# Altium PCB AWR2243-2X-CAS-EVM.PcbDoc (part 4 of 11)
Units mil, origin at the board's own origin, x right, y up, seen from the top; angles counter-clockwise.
Board outline 5118.11 x 3937.01 mil, 8 copper layers (Layer 1 - Top Layer, Layer 2 - GND, Layer 3 - Signal (Sensitive), Layer 4 - GND / Signal, Layer 5 - Signal, Layer 6 - PWR / Signal, Layer 7 - GND, Layer 8 - Bottom Layer), stack 54.8 mil thick; 629 components, 407 nets, 2243 pads, 3950 vias.
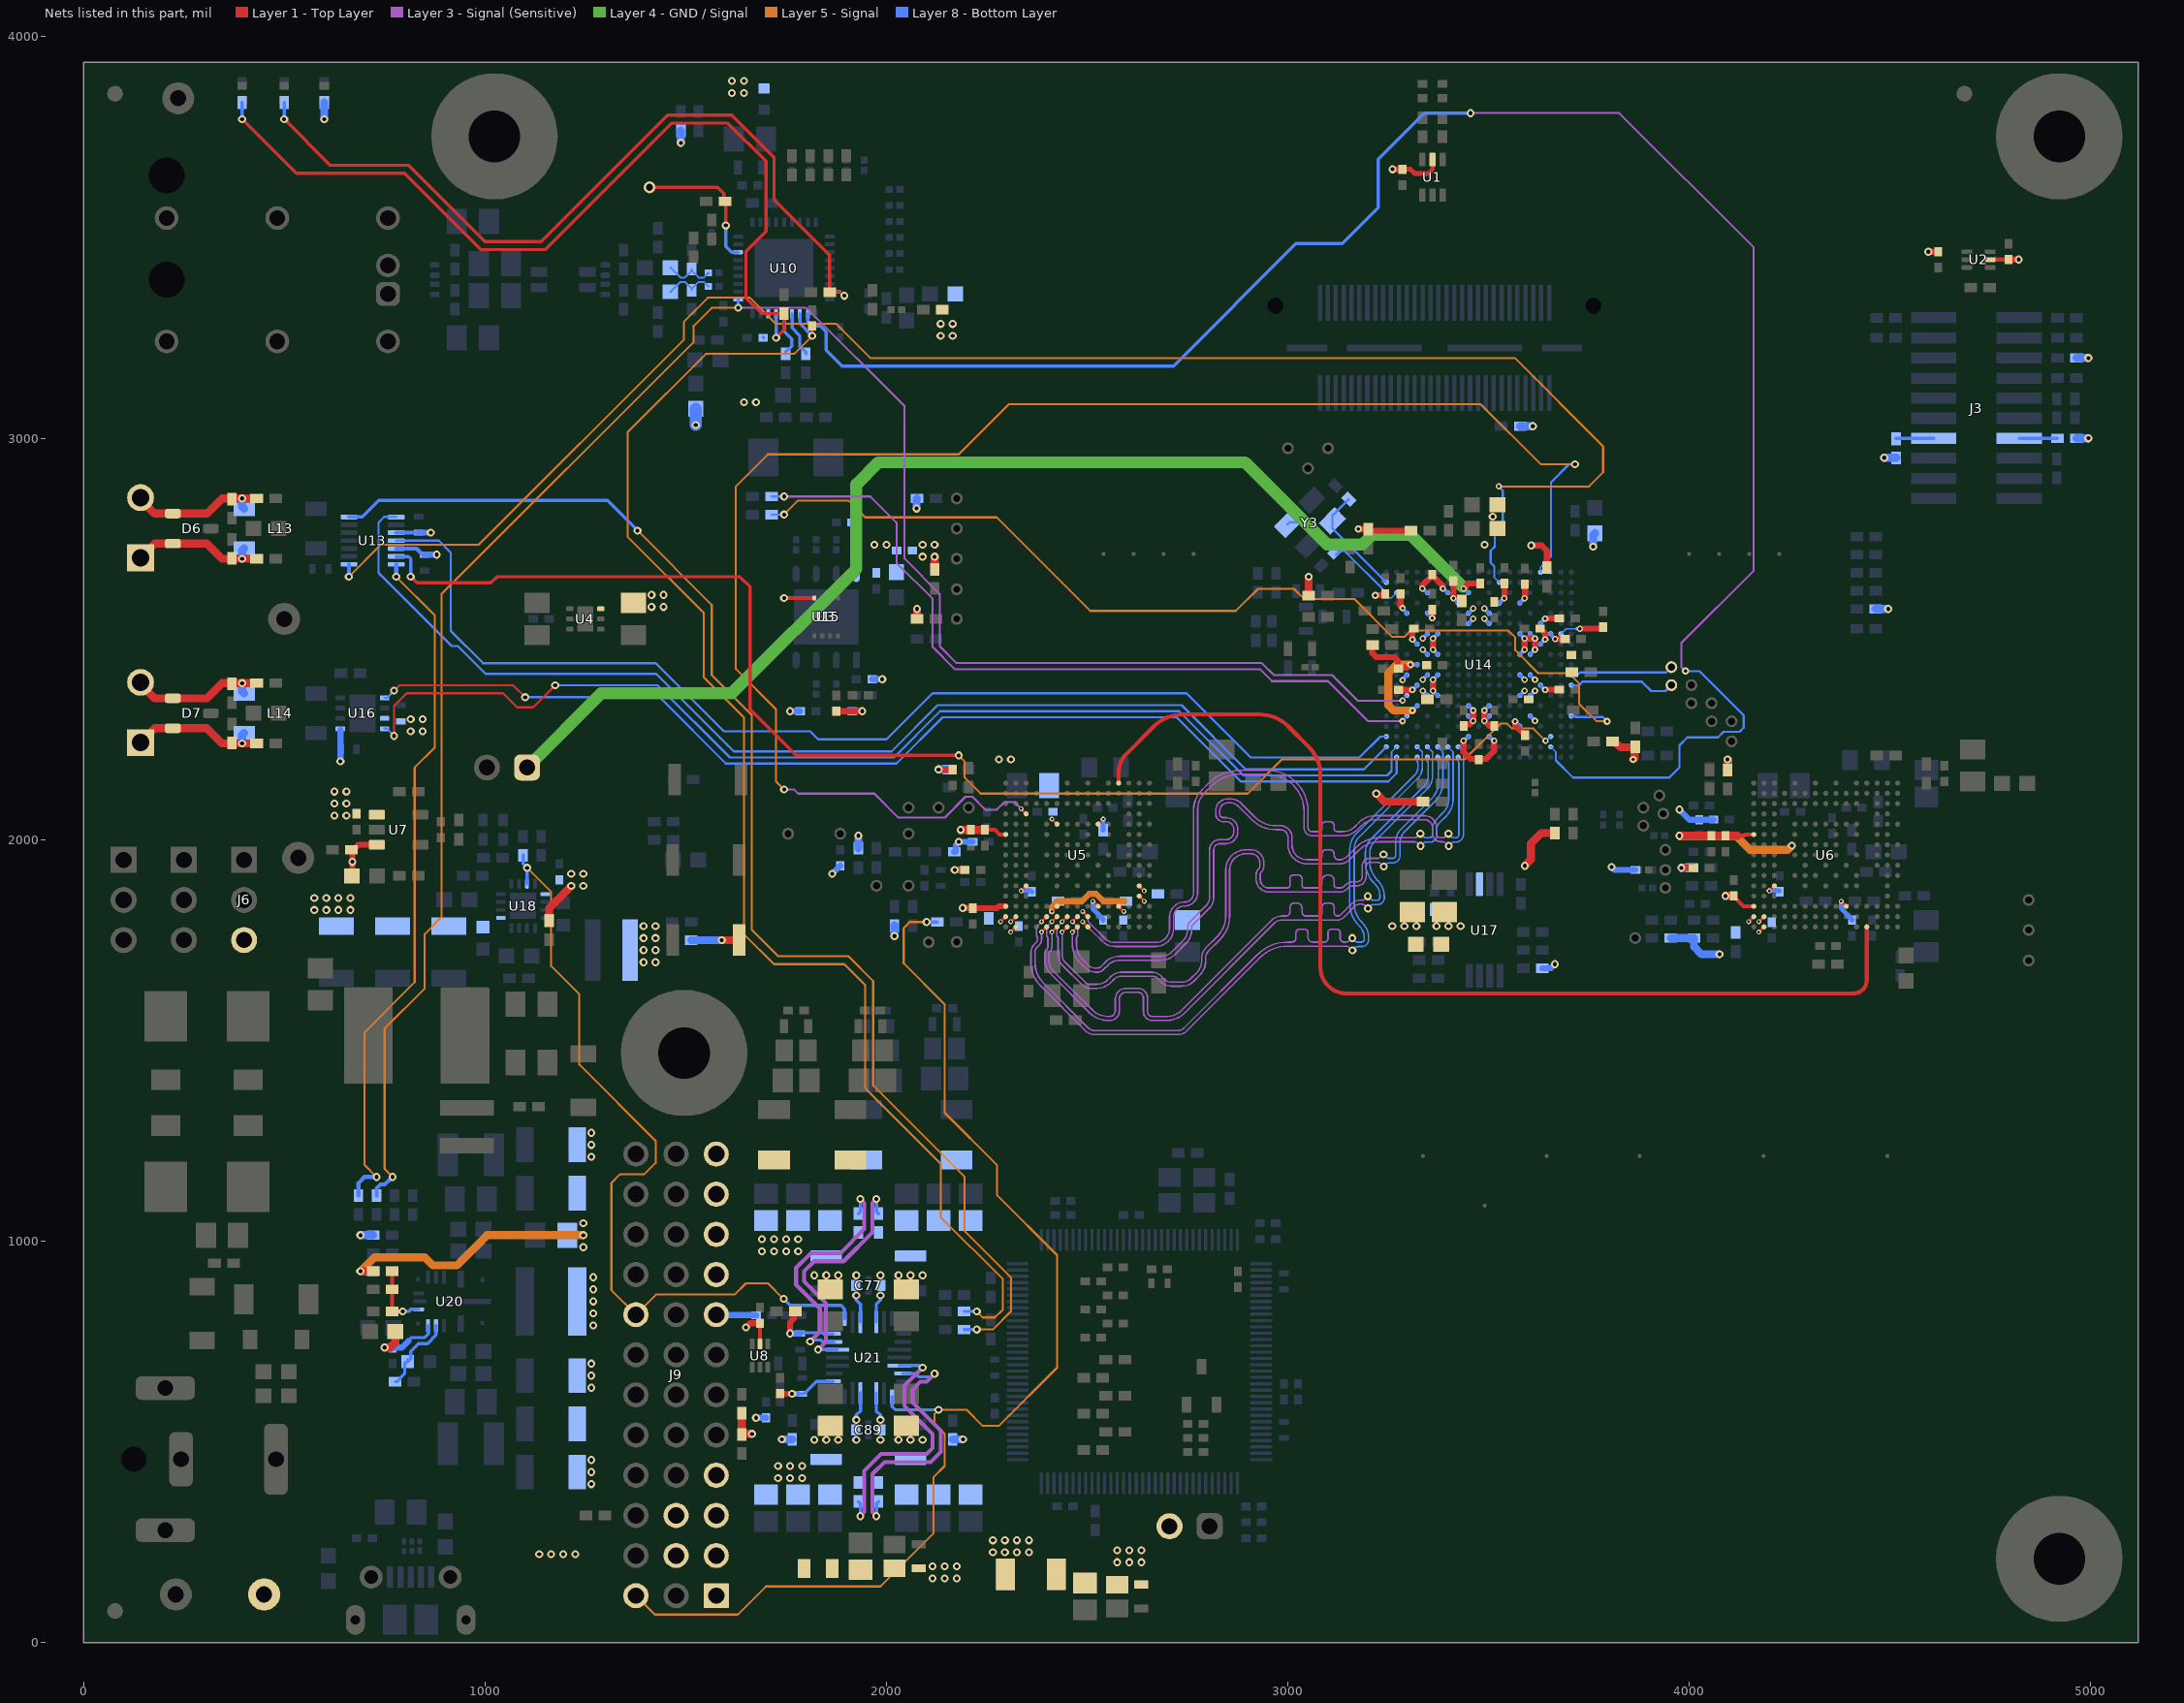
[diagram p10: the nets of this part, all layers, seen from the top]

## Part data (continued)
U1: library part CMP-0051906-3, "Automotive Catalog Dual Schmitt-Trigger Buffer, DCK0006A (SOT-SC70-6)", F @ Nom Voltage(Max)(Mhz)=150, Generic Part Number=SN74LVC2G17-Q1, ICC @ Nom Voltage(Max)(mA)=0.01, Manufacturer="Texas Instruments", Operating Temperature Range="-40 to 125 C", Rating=Automotive, tpd @ Nom Voltage(Max)(ns)=9.3,5.7,5.4,4.3, Voltage(Nom)(V)=1.8,2.5,3.3,5
U2 U8: library part CMP-0067397-2, "1.4V-Capable +/-0.5degC Temperature Sensor with Alert Function and I2C/SMBus interface in SOT-563, DRL0006A (SOT-OTHER-6)", Alternate Manufacturer="Texas Instruments", Alternate PartNumber=TMP112AIDRLT
U3: library part CMP-0089721-1, "FLASH - NOR Memory IC 16Mb (2M x 8) SPI 80MHz 8-USON (2x3)", Frequency_Fixed=80MHz, Manufacturer=Macronix, Max Supply Voltage=3.6V, Min Supply Voltage=2.3V, Nominal Supply Current=3.5-6.5mA, Operating Temperature Range="-40°C to +85°C"
U4: library part CMP-0860463-1, "Automotive 150-mA high-voltage ultra-low-IQ low-dropout (LDO) linear regulator, DRV0006A (WSON-6)", Alternate Manufacturer="Texas Instruments", Operating Temperature Range="-40 to 150 C", Rating=Automotive
U5 U6: library part CMP-0082537-1, "Single Chip 77 and 79 GHz FMCW Transceiver, ABL0161A (FCBGA-161)", Alternate Manufacturer="Texas Instruments", Rating=Automotive
U7: library part CMP-0860753-1, "300-mA, Low-IQ Low-Dropout Regulator, DBV0005A (SOT-23-5)", Alternate Manufacturer="Texas Instruments"
U9: library part CMP-0033001-1, "Precision Micropower Shunt Voltage Reference, 0.5% accuracy, 2.5 V, 15 ppm / degC, 15 mA, -40 to 125 degC, 3-pin SOT-23 (DBZ), Green (RoHS & no Sb/Br)", Manufacturer="Texas Instruments", Rating=Catalog, Temp Coeff(Max)(ppm/ degree C)=100, Temp Coeff(Typ)(ppm/ degree C)=15
U10: library part CMP-0089064-1, "TC-10 Compliant 100Base-T1 Automotive Ethernet PHY", Manufacturer="Texas Instruments", Operating Temperature Range="-40°C to +125°C"
U11 U12: library part CMP-0073592-4, "Automotive 1-Channel ESD in 0402 Package With 12pF Capacitance and 6V Breakdown, DPY0002A (X1SON-2)", Alternate Manufacturer="Texas Instruments", Alternate PartNumber=TPD1E10B06DPYR, Operating Temperature Range="-40 to 125 C", Rating=Automotive
U13: library part CMP-0089855-1, "Low-Power Fault Protected CAN FD Transceiver with INH and WAKE", Manufacturer="Texas Instruments", Max Supply Voltage=28V, Min Supply Voltage=1.7V, Operating Temperature Range="-40°C to +125°C"
U14: library part CMP-0088502-3, "No description", Manufacturer="Texas Instruments", Operating Temperature Range=to
U15: library part CMP-0091167-2, "3.3V Uniform Sector Dual and Quad Serial Flash", Frequency_Fixed=120MHz, Manufacturer=GigaDevice, Max Supply Voltage=3.6V, Min Supply Voltage=2.7V, Operating Temperature Range="-40°C to +105°C"
U16: library part CMP-0079884-2, "Automotive High Speed CAN Transceiver, DRB0008J (VSON-8)", Alternate Manufacturer="Texas Instruments", Alternate PartNumber=TCAN1044VDRBRQ1
U17: library part CMP-0091149-1, Digikey Part Number=296-LMK1C1102PWRCT-ND, Manufacturer="Texas Instruments", Max Supply Voltage=3.465V, Min Supply Voltage=1.71V, Mouser Part Number=595-LMK1C1102PWR, Nominal Supply Current=25-33000uA, Operating Temperature Range="-40°C to +125°C"
U18: library part CMP-0089188-3, "25-µA Quiescent Current Synchronous Boost Converter with Load Disconnect", Manufacturer="Texas Instruments", Max Supply Voltage=14V, Min Supply Voltage=2.3V, Nominal Supply Current=25uA, Operating Temperature Range="-40°C to +175°C", Output Voltage=3-18.5V, Switching Frequency=200-2200kHz
U19: library part CMP-0029856-2, "Tiva C Series Microcontroller, 1024 KB Flash, 256 KB SRAM, 12 Bit, 20 Channels, -40 to 105 degC, 128-Pin TQFP (PDT), Green (RoHS & no Sb/Br), Tray", Manufacturer="Texas Instruments", Temperature Range="-40 to 105 degC"
U20: library part CMP-0860179-2, "LM62460QRPHRQ1, RPH0016A (VQFN-HR-16)", Alternate Manufacturer="Texas Instruments"
U21: library part CMP-0091103-2, "Four-Phase, 20-A Buck Converter With Integrated Switches", Manufacturer="Texas Instruments", Max Supply Voltage=5.5V, Min Supply Voltage=2.8V, Nominal Supply Current=3uA, Operating Temperature Range="-40°C to +150°C", Output Voltage=0.3-3.34V, Switching Frequency=2.2-4.4-8.8MHz
U22: library part CMP-0043115-3, "4-Channel ESD Protection Array for High-Speed Data Interfaces, DRY0006A (USON-6)", Breakdown Voltage(Min)(V)=6, IO Capacitance(Typ)(pF)=1.6, IO Leakage Current(nA)=1, Manufacturer="Texas Instruments", Operating Temperature Range="-40 to 85 C", Rating=Catalog
Y1 Y3: library part CMP-0004694-2, "Crystal, 40 MHz, 8pF, SMD", Frequency_Fixed=40MHz, Frequency Stability=+/-200ppm, Manufacturer=Kyocera, Supplier Part Number 1=581-CX3225SA40D0PTWC
Y2: library part CMP-0004614-3, "Crystal, 25 MHz, 18 pF, SMD", Frequency_Fixed=25MHz, Frequency Stability=+/-25ppm, Manufacturer="Abracon Corporation"
Y4: library part CMP-0078214-2, "Crystal, 16 MHz, 15 ppm, 8 pF, AEC-Q200 Grade 1, SMD", Frequency_Fixed=16MHz, Frequency Stability="150 ppm", Frequency Tolerance="10 ppm", Load Capacitance="7.36 pF", Manufacturer=NDK, Supplier Part Number 1=644-1129-1-ND
ZZ1: library part CMP-0003616-3
ZZ2: library part CMP-0077236-1
ZZ3: library part CMP-0077237-1
ZZ4: library part CMP-0077238-1

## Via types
v1: diameter 13.78, hole 5.91, Layer 1 - Top Layer to Layer 2 - GND, tented top, 2104 vias
v2: diameter 20, hole 10, Layer 1 - Top Layer to Layer 8 - Bottom Layer, tented both sides, 831 vias
v3: diameter 7.87, hole 3.94, Layer 1 - Top Layer to Layer 2 - GND, tented top, 510 vias
v4: diameter 12, hole 6, Layer 1 - Top Layer to Layer 8 - Bottom Layer, tented both sides, 176 vias
v5: diameter 16, hole 8, Layer 1 - Top Layer to Layer 8 - Bottom Layer, tented both sides, 138 vias
v6: diameter 13.78, hole 5.91, Layer 1 - Top Layer to Layer 2 - GND, tented both sides, 88 vias
v7: diameter 18, hole 8, Layer 1 - Top Layer to Layer 8 - Bottom Layer, tented both sides, 41 vias
v8: diameter 22, hole 12, Layer 1 - Top Layer to Layer 8 - Bottom Layer, tented both sides, 36 vias
v9: diameter 19.68, hole 7.87, Layer 1 - Top Layer to Layer 8 - Bottom Layer, tented both sides, 26 vias

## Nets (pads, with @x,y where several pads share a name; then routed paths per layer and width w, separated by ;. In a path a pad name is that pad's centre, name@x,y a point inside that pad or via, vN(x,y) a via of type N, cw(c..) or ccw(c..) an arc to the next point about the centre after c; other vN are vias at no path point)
1V0_A: C200.1 C201.1 C202.1 J9.25 J9.28 L5.1 L6.1 L19.2 R210.1
  other v2: 1690,975 1720,975 1750,975 1780,975 1690,1005 1720,1005 1750,1005 1780,1005
1V0_B: C197.1 C198.1 C199.1 J9.31 J9.34 L16.1 L17.1 L18.2 R209.1
1V2: C4.2 C6.2 C9.2 C18.1 C19.2 C20.2 C24.2 C26.2 C27.2 C29.1 C33.1 C34.2 C36.2 C37.2 C233.1 C234.1 C235.1 J9.7 J9.10 L8.1 L22.2 R227.1 U14.E9 U14.E11 U14.F9 U14.F11 U14.G5 U14.G6 U14.G14 U14.G15 U14.J3 U14.J5 U14.J6 U14.J14 U14.J15 U14.L5 U14.L6 U14.L14 U14.L15 U14.N5 U14.N6 U14.N14 U14.N15 U14.N17 U14.N18 U14.P9 U14.P11 U14.R9 U14.R11 U14.T8 | length 869.9
  Layer 1 - Top Layer w15: v5(3361.16,2371.24) 3361.21,2371.29 3361.21,2398.73 v5(3361.27,2398.79) ; v5(3361.16,2473.6) v5(3361.16,2501.04) ; v5(3412.34,2601.56) 3412.34,2643.31 C9.2@3413.34,2644.3 ; C37.2@3437.83,2283.32 3439.24,2284.73 3439.24,2286.7 3451.78,2286.7 3461.4,2296.32 v5(3461.67,2296.32) v5(3461.67,2321.91) ; v5(3489.11,2321.91) v5(3489.11,2296.32) 3502.08,2283.35 C36.2@3512.65,2283.35 ; v5@3489.11,2575.75 v5(3489.22,2575.86) ; v5(3589.63,2473.6) v5(3589.63,2501.04) v5(3615.22,2501.04) v5(3615.22,2473.6) ; v5(3665.18,2500.12) 3665.31,2499.99 3690.34,2499.99 C24.2@3690.47,2499.87 ; v5(3727.34,2525.71) 3727.53,2525.9 3777.08,2525.9 C20.2@3778.84,2527.65
  Layer 8 - Bottom Layer w4: U14.N18@3680.12,2512.91 3692.91,2525.71 3718,2525.71
  Layer 8 - Bottom Layer w8: 3718,2525.71 v5(3727.34,2525.71)
  Layer 8 - Bottom Layer w10: v5(3285.61,2397.76) U14.J3@3296.26,2410.55 ; v5(3335.57,2371.24) U14.G5@3347.33,2359.48 ; v5(3335.57,2473.6) U14.L5@3347.33,2461.84 ; v5(3335.57,2501.04) U14.N5@3347.33,2512.81 ; v5(3335.68,2398.79) U14.J5@3347.44,2410.55 ; v5(3361.16,2371.24) U14.G6@3372.93,2359.48 ; v5(3361.16,2473.6) U14.L6@3372.93,2461.84 ; v5(3361.16,2501.04) U14.N6@3372.93,2512.81 ; v5(3361.27,2398.79) U14.J6@3373.03,2410.55 ; v5(3412.34,2601.56) U14.T8@3424.21,2589.69 ; U14.E9@3449.91,2308.08 v5(3461.67,2296.32) ; U14.F9@3449.91,2333.67 v5(3461.67,2321.91) ; U14.P9@3449.91,2538.61 v5(3461.67,2550.37) ; U14.R9@3449.91,2564.2 v5(3461.67,2575.96) ; v5(3489.11,2296.32) U14.E11@3500.88,2308.08 ; v5(3489.11,2321.91) U14.F11@3500.88,2333.67 ; v5(3489.11,2550.37) U14.P11@3500.88,2538.61 ; v5(3489.22,2575.86) U14.R11@3500.98,2564.09 ; U14.L14@3577.75,2461.73 v5(3589.63,2473.6) ; U14.G14@3577.86,2359.48 v5(3589.63,2371.24) ; U14.J14@3577.86,2410.45 v5(3589.63,2398.68) ; U14.N14@3577.86,2512.81 v5(3589.63,2501.04) ; U14.L15@3603.35,2461.73 v5(3615.22,2473.6) ; U14.N15@3603.35,2512.91 v5(3615.22,2501.04) ; U14.G15@3603.45,2359.48 v5(3615.22,2371.24) ; U14.J15@3603.45,2410.45 v5(3615.22,2398.68) ; U14.N17@3654.53,2512.91 3655.1,2512.34 3655.1,2510.2 v5(3665.18,2500.12)
  other v2: 1730,410 1760,410 1790,410 1730,440 1760,440 1790,440 3490,2735 3510,2805
1V2_FILTERED: C50.1 C51.1 C52.1 C53.1 C92.1 C93.1 C94.1 C156.1 C157.1 C170.1 C172.1 C174.1 C175.1 C180.1 C181.1 L8.2 R223.2 U5.F13 U5.N11 U5.P14 U5.P15 U5.R6 U5.R14 U6.F13 U6.N11 U6.P14 U6.P15 U6.R6 U6.R14 | length 976.7
  Layer 1 - Top Layer w7: v4(2284.05,1795.67) U5.R14@2296.85,1808.46 ; v4(2309.65,1770.08) U5.P15@2322.44,1782.87 ; v4(2309.65,1795.67) U5.P14@2322.44,1808.46 ; v4(2335.24,1872.44) U5.N11@2348.03,1885.24 ; v4(2514.37,1846.85) U5.F13@2527.17,1834.06 ; v4(4147.44,1795.67) U6.R14@4160.24,1808.46 ; v4(4173.03,1770.08) U6.P15@4185.83,1782.87 ; v4(4173.03,1795.67) U6.P14@4185.83,1808.46 ; v4(4198.62,1872.44) U6.N11@4211.42,1885.24 ; v4(4377.76,1846.85) U6.F13@4390.55,1834.06
  Layer 1 - Top Layer w10: C51.1@2245,2024.68 2270.32,2024.68 2281.81,2013.19 U5.R6@2296.85,2013.19 ; 4120,2010 4135,2010 4138.19,2013.19 U6.R6@4160.24,2013.19
  Layer 1 - Top Layer w20: v2(2185,2024.68) C50.1@2210,2024.68 C51.1@2245,2024.68 ; v2(3975,2010) 4054.68,2010 C52.1@4055,2009.68 C53.1@4090,2009.68 4119.68,2009.68 4120,2010
  Layer 5 - Signal w20: v2(3975,2010) 4115,2010 4150,1975 4245,1975 v2(4255,1985)
  Layer 8 - Bottom Layer w12: v4(2335.24,1872.44) 2359.87,1872.44 C157.1@2362,1870.32 ; v4(2514.37,1846.85) 2514.37,1827.28 2540,1801.65 C174.1@2540,1799.68 ; v4(4198.62,1872.44) C156.1@4223.26,1872.44 ; v4(4377.76,1846.85) 4377.76,1828.9 4405,1801.65 C172.1@4405,1799.68
  Layer 8 - Bottom Layer w15: v2(1675,560) 1699.69,560 R223.2@1700,560.31
  other v2: 2115,160 2145,160 2175,160 2115,190 2145,190 2175,190
1V7: C10.2 P1.1 U14.U9 | length 2980.7
  Layer 1 - Top Layer w15: v5(3437.01,2625.93) 3449.39,2638.31 C10.2@3479,2638.31
  Layer 4 - GND / Signal w30: P1.1@1105,2180 1290,2365 1615,2365 1925,2675 1925,2885 1980,2940 2893.23,2940 3098.23,2735 3185,2735 3210,2760 3305,2760 v5@3435,2630
  Layer 8 - Bottom Layer w10: v5(3437.01,2625.93) U14.U9@3449.8,2615.28
1V8: C8.2 C12.2 C13.2 C14.2 C22.2 C23.2 C32.2 C42.2 C230.1 C231.1 C232.1 J9.1 J9.4 L7.1 L21.2 L23.1 R226.1 U14.C9 U14.C11 U14.E15 U14.H4 U14.M4 U14.M16 U14.R3 U14.T14 U14.U2 U14.U5 U14.U7 | length 659.7
  Layer 1 - Top Layer w8: v5@3309.69,2373.38 v5(3309.98,2373.09)
  Layer 1 - Top Layer w15: v7@3217.34,2609.19 v7(3217.84,2608.69) 3218.41,2609.26 3240.34,2609.26 3242.68,2611.6 C14.2@3242.68,2612.37 ; C32.2@3275.57,2373.38 v5@3309.69,2373.38 ; C13.2@3280.29,2612.37 3280.29,2582.48 3285.61,2577.16 v5(3285.61,2576.89) ; v5(3309.98,2499.19) 3309.98,2522.27 C22.2@3313.42,2525.71 ; v5(3334.65,2625.93) 3334.38,2625.93 3334.84,2626.39 3334.84,2633.78 C8.2@3359.76,2658.7 ; C8.2@3359.76,2660.67 C8.2@3359.76,2658.7 ; v5(3385.83,2625.93) 3385.64,2626.12 3385.64,2632.82 C8.2@3359.76,2658.7 ; v5(3437.01,2246.35) 3437.2,2246.16 3437.2,2219.02 3454.67,2201.55 3475.39,2201.55 C42.2@3475.39,2199.58 3477.17,2201.35 3493.83,2201.35 3513.59,2221.11 3513.59,2246.16 v5(3513.78,2246.35) ; v5(3589.63,2601.56) 3590.39,2602.31 C12.2@3590.39,2636.55 ; C23.2@3628.07,2525.58 3630.04,2525.58 3640.62,2515.01 3640.62,2499.38 v5(3640.81,2499.19)
  Layer 8 - Bottom Layer w4: v7(3217.84,2608.69) 3229.31,2608.69 3235.52,2602.48 3257.87,2602.48 U14.U2@3270.67,2615.28
  Layer 8 - Bottom Layer w10: v5(3285.61,2576.89) U14.R3@3296.26,2564.09 ; v5(3309.98,2373.09) U14.H4@3321.85,2384.96 ; v5(3309.98,2499.19) U14.M4@3321.74,2487.43 ; v5(3334.65,2625.93) U14.U5@3347.44,2615.28 ; v5(3385.83,2625.93) U14.U7@3398.62,2615.28 ; v5(3437.01,2246.35) U14.C9@3449.8,2257.01 ; U14.C11@3500.98,2257.01 v5(3513.78,2246.35) ; U14.T14@3577.75,2589.69 v5(3589.63,2601.56) ; U14.E15@3603.35,2308.19 v5(3615.22,2296.32) ; U14.M16@3629.04,2487.43 v5(3640.81,2499.19)
  other v2: 2265,225 2295,225 2325,225 2355,225 2265,255 2295,255 2325,255 2355,255
3V3: C1.2 C2.2 C11.2 C15.2 C21.2 C28.2 C31.2 C39.2 C48.2 C54.1 C56.1 C57.1 C77.1 C77.3 C78.1 C79.1 C82.1 C83.1 C86.1 C87.1 C89.1 C89.3 C116.2 C119.1 C130.1 C153.2 C192.1 C196.1 C207.1 C213.2 C215.2 C216.1 C219.1 C226.1 C229.1 FB1.1 J6.3 J9.5 J9.8 L1.1 L15.1 L20.2 P2.2 R10.1 R15.2 R20.2 R21.2 R24.2 R25.2 R29.2 R31.2 R35.2 R36.2 R42.2 R43.2 R48.2 R49.2 R52.2 R53.2 R55.1 R56.2 R58.2 R63.2 R70.1 R74.1 R76.2 R81.2 R117.2 R122.2 R123.2 R124.2 R127.2 R135.2 R141.2 R155.2 R157.2 R164.2 R165.2 R170.2 R172.2 R173.2 R175.2 R178.2 R180.2 R181.2 R189.2 R196.2 R197.2 R213.1 R215.2 R224.2 R225.2 R236.1 R237.1 TP42.1 U1.5 U2.5 U3.8 U5.R13 U6.R13 U7.1 U7.3 U8.5 U13.5 U14.D14 U14.F4 U14.H16 U14.K4 U14.P16 U14.R5 U14.T12 U16.5 U18.1 U20.5 U21.12 U21.14 U21.18 U21.24 U21.28 U21.30 | length 4857.2
  Layer 1 - Top Layer w5.5: v5@3304.97,2436.18 v5(3305.01,2436.14)
  Layer 1 - Top Layer w10: U8.5@1685,744.13 C82.1@1685,795.32 ; v2(1745,2602.24) U3.8@1819,2602.24 ; C56.1@4110,1858.35 4134.29,1834.06 U6.R13@4160.24,1834.06 ; U2.5@4749.13,3445 4749.29,3445.16 4794.84,3445.16 C2.2@4795,3445.31
  Layer 1 - Top Layer w12: C1.2@3285,3669.69 3285.31,3670 3305,3670 3315,3660 3350,3660 3360,3670 U1.5@3360,3694.29
  Layer 1 - Top Layer w15: R55.1@673.5,1910 670,1913.5 v2(670,1945) 670,1972.87 R52.2@667.87,1975 671.81,1975 684.41,1987.6 U7.3@730.87,1987.6 ; v2(1650,785) 1660.31,795.32 C82.1@1685,795.32 ; R74.1@1735,620.32 1735.16,620.16 1764.84,620.16 v2(1765,620) ; v2(1760,770) 1760,798.44 1770,808.44 1770,821.38 R70.1@1773.62,825 ; v2(2130,2175) R43.2@2160.31,2175 ; v2(2170,1925) R56.2@2195.31,1925 ; v2(2190,1830) 2214.68,1830 C57.1@2215,1829.68 2274.68,1829.68 2279.06,1834.06 U5.R13@2296.85,1834.06 ; v7(3175,2774.31) 3199.31,2774.31 R20.2@3200,2773.62 3203.62,2770 R21.2@3306.38,2770 ; R31.2@3211.38,2485 3210,2483.62 3210,2465 3220,2455 3265,2455 3273.79,2446.21 3273.79,2428.08 C28.2@3275.52,2426.35 3277.86,2428.69 3297.29,2428.69 3304.74,2436.14 v5(3305.01,2436.14) ; v2(3260.31,3670) C1.2@3285.31,3670 ; C15.2@3359.12,2573.4 3359.12,2552.42 v5(3359.31,2552.23) ; v5(3538.44,2601.56) 3539.34,2602.45 C11.2@3539.34,2638.25 ; v5(3565.89,2294.47) 3565.89,2285.22 C39.2@3590.54,2260.57 ; v2(3606,2733) 3632,2733 3645,2720 R24.2@3645,2678.62 ; v5(3640.81,2373.09) 3641.3,2373.58 C31.2@3675.4,2373.58 ; v5(3640.81,2550.37) 3641.08,2550.37 3641.75,2551.05 C21.2@3676,2551.05 ; v2(3980,1930) R53.2@4010.31,1930 ; v2(4594.84,3464.53) R10.1@4619.84,3464.53 ; C2.2@4795,3445.31 v2(4820,3445.31)
  Layer 1 - Top Layer w20: v2(690,925) R63.2@721.38,925 ; v2(750,735) 765,735 776.5,746.5 C83.1@776.5,775 C83.1@781.5,770 ; R58.2@1160,1798.62 1160,1830 v2(1215,1885) ; R81.2@1640,518.62 1641.38,520 v2(1665,520) ; R81.2@1640,520 R76.2@1640,571.38 ; R29.2@2076.38,2550 v2(2076.38,2575) ; R25.2@2120,2673.62 v2(2120,2705) ; v2(3220,2115) 3240,2095 R48.2@3336.38,2095 ; v2(3590,1935) 3605,1950 3605,1990 3631.38,2016.38 R49.2@3665,2016.38 ; R36.2@3808.62,2245 3812.56,2245 3827.56,2230 R35.2@3863.62,2230 ; v7(3860,2200) 3863.19,2203.19 3863.19,2229.57 R35.2@3863.62,2230 ; R35.2@3865,2231.38 R35.2@3863.62,2230 ; v2(4090,1860) C56.1@4109.84,1860 ; R42.2@4095,2173.62 v2(4095,2200)
  Layer 5 - Signal w20: v2(690,925) 725,960 850,960 870,940 930,940 1005,1015 v2(1245,1015) ; v5(3305.01,2436.14) 3271.14,2436.14 3250,2415 3250,2335 3263.09,2321.91 v5(3309.98,2321.91)
  Layer 8 - Bottom Layer w8: 809,751 818,760 850,760 858.37,768.37 U20.5@858.37,789.45 ; 1777.5,620 C219.1@1790,620 1795,620 1825.94,650.94 U21.18@1867.4,650.94 ; C213.2@1785,772 1841,772 1843.94,769.06 U21.24@1867.4,769.06 ; v2(1925,555) 1925,567 1935.32,577.32 U21.14@1935.31,621.42 ; v2(1925,865) 1925,853 1935.32,842.68 U21.28@1935.31,798.58 ; U21.12@1974.68,621.42 1974.69,577.32 1985,567 v2(1985,555) ; U21.30@1974.68,798.58 1974.69,842.68 1985,853 v2(1985,865)
  Layer 8 - Bottom Layer w10: U13.5@779.06,2725.32 829.68,2725.32 845,2710 C119.1@850,2710 ; v5(3305.01,2436.14) U14.K4@3321.85,2436.14 ; v5(3309.98,2321.91) U14.F4@3321.85,2333.78 ; U14.R5@3347.44,2564.09 v5(3359.31,2552.23) ; U14.T12@3526.57,2589.69 v5(3538.44,2601.56) ; v5(3565.89,2294.47) U14.D14@3577.75,2282.6 ; U14.H16@3629.04,2384.86 v5(3640.81,2373.09) ; U14.P16@3629.04,2538.61 v5(3640.81,2550.37)
  Layer 8 - Bottom Layer w15: v2(640,2195) U16.5@640,2274 ; v2(750,735) 769.69,735 C215.2@770,734.69 ; C215.2@770,735.69 770.69,735 793,735 809,751 ; C119.1@850,2710 v2(880,2710) ; v2(1760,770) C213.2@1785,770 ; v2(1765,620) 1777.5,620 ; v2(1865,1915) 1865,1915.31 R175.2@1885,1935.31 ; R173.2@2168.62,1970 2172.56,1970 2173,1970.44 2173,1986.65 2180,1993.65 v2(2180,1995) R170.2@2215,1995 ; v2(2170,1925) R181.2@2195.31,1925 ; v2(3806,1932) 3813,1925 R180.2@3865.55,1925 ; v2(3975,2075) 4000,2050 R165.2@4060.31,2050
  Layer 8 - Bottom Layer w20: v2(690,925) R215.2@721.38,925 ; v2(690,1015) R213.1@721.38,1015 ; v2(1739.74,506.38) R225.2@1765.21,506.38 ; R172.2@1930,1978.62 v2(1930,2010) ; v2(2020,1760) R189.2@2020,1786.38 ; v2(2075,2825) 2075,2848.62 R127.2@2076.38,2850 ; v2(2130,2175) R157.2@2156.38,2175 ; R224.2@2165,506.38 v2(2190.47,506.38) ; R122.2@3578.62,3030 v2(3610,3030) ; v2(3760,2730) 3760,2758.5 C116.2@3765,2763.5 ; R197.2@3953.62,1755 R196.2@4011.38,1755 4011.38,1733.62 4030,1715 v2(4075,1715) ; v2(3980,1930) R178.2@4006.38,1930 ; R155.2@4095,2173.62 v2(4095,2200) ; R141.2@4463.62,2575 v2(4495,2575) ; v2(4485,2951.38) R123.2@4515,2951.38 ; R124.2@4963.62,3000 v2(4993.62,3000) ; R117.2@4963.62,3200 v2(4993.62,3200)
  Layer 8 - Bottom Layer w30: v2(1525,3033) R237.1@1525,3073.5
  other v2: 1265,395 1265,425 1265,455 1820,505 1850,505 1880,505 1925,505 1985,505 2030,505 2060,505 2090,505 1265,635 1265,665 1265,695 1270,790 1270,820 1270,850 1270,880 1270,910 1820,915 1850,915 1880,915 1925,915 1985,915 2030,915 2060,915 2090,915 1245,985 1245,1045 1265,1210 1265,1240 1265,1270 1395,1695 1425,1695 1395,1725 1425,1725 1395,1755 1425,1755 1395,1785 1425,1785 3260,1785 3290,1785 3320,1785 1245,1885 1215,1915 1245,1915 625,2060 655,2060 625,2090 655,2090 625,2120 655,2120 2090,2705 2090,2735 2120,2735 2135,3255 2165,3255 2135,3285 2165,3285 1615,3860 1645,3860 1615,3890 1645,3890
3V3_BUFFER: C55.2 C158.2 C159.1 L1.2 R202.2 U17.6 | length 35.5
  Layer 8 - Bottom Layer w15: R202.2@3633.62,1680 3655,1680 v2(3665,1690)
  other v2: 3370,1785 3400,1785 3430,1785
3V3_FLASH: C120.2 C122.2 R130.2 R135.1 R150.2 R151.2 R152.2 R240.2 U15.8 | length 141.1
  Layer 1 - Top Layer w15: R240.2@1875,2320.31 1939.69,2320.31 v2(1940,2320)
  Layer 8 - Bottom Layer w15: v2(1760,2320) R152.2@1785.31,2320 ; R151.2@1914.68,2320 v2(1940,2320) ; R150.2@1964.27,2400 v2(1989.59,2400)
  other v2: 1970,2735 2000,2735
3V3_LDO: C17.1 C111.2 C182.1 R84.2 R88.2 S3.1 U4.6 U10.7 | length 193.6
  Layer 1 - Top Layer w20: v2(1590,1750) S3.1@1632.68,1750
  Layer 8 - Bottom Layer w8: C111.2@1692.69,3252 C111.2@1694.69,3250
  Layer 8 - Bottom Layer w20: v2(600,3795) R84.2@600,3836.38 ; v2(1488,3736) R88.2@1488,3766.38 ; C182.1@1513.62,1750 v2(1590,1750)
  other v2: 1415,2580 1445,2580 1415,2610 1445,2610 1645,3090 1675,3090
5V: C117.1 C129.1 C176.1 C177.1 C178.1 C179.1 J9.22 R220.2 U13.3 U16.3 U18.9 | length 186.1
  Layer 8 - Bottom Layer w10: U13.3@779.06,2764.69 C117.1@835,2764.69
  Layer 8 - Bottom Layer w15: C117.1@835,2765 v2(865,2765) ; J9.22@1575.98,817.01 1576.99,816 1674.31,816 R220.2@1675.31,815
  other v2: 575,1825 605,1825 635,1825 665,1825 575,1855 605,1855 635,1855 665,1855 815,2270 845,2270 815,2300 845,2300
25MHZ_XTAL: R129.1 U14.E19 | length 2525.1
  Layer 5 - Signal w5: v2(1745,2810) 1780,2845 1905,2845 1947,2803 2274.57,2803 2507.57,2570 2870,2570 2925,2625 3015,2625 3040,2600 3165,2600 3259.07,2505.93 3290.93,2505.93 3306,2521 3549,2521 3566,2504 3566,2472 3623,2415 3700,2415 3725,2390 3725,2339 3769,2295 v7(3795,2295)
  Layer 8 - Bottom Layer w5: R129.1@1713.62,2810 v2(1745,2810)
  Layer 8 - Bottom Layer w5.5: U14.E19@3705.71,2308.19 3707.14,2306.75 3717.37,2306.75 3718.73,2305.39 3784.61,2305.39 v7(3795,2295)
BOOST_ENABLE: J9.24 R167.2 U18.15 U21.26 | length 2029.2
  Layer 5 - Signal w5: v2(1105,1930) 1165,1870 1165,1685 1235,1615 1235,1440 1425,1250 1425,1195 1397,1167 1337,1167 1315,1145 1315,877.99 J9.24@1375.98,817.01 1425.98,867 1622,867 1650,895 1705,895 v2@1744,856
  Layer 8 - Bottom Layer w8: R167.2@1095,1961.38 1095,1940 1104.84,1930.16 U18.15@1104.84,1890.12 ; v2@1744,856 1760,840 1887,840 1895.94,831.06 U21.26@1895.94,807.44
  other v2: 1744.33,856.33
CAN1_HI: C30.1 D7.1 J5.2 L14.4 R33.1 | length 342.3
  Layer 1 - Top Layer w20: J5.2@142.24,2387.99 177.83,2352.4 D7.1@222.76,2352.4 307.4,2352.4 345,2390 R33.1@426.38,2390
  Layer 8 - Bottom Layer w20: v2(395,2390) 395,2369.23 L14.4@400.02,2364.21
CAN1_LOW: C38.1 D7.2 J5.1 L14.3 R38.2 | length 342.3
  Layer 1 - Top Layer w20: J5.1@142.24,2242.01 177.83,2277.6 D7.2@222.76,2277.6 307.4,2277.6 345,2240 v2(395,2240) R38.2@426.38,2240
  Layer 8 - Bottom Layer w20: v2(395,2240) 395,2260.77 L14.3@400.02,2265.79
CAN2_HI: C3.1 D6.1 J4.2 L13.4 R18.1 | length 342.3
  Layer 1 - Top Layer w20: J4.2@142.24,2847.99 177.83,2812.4 D6.1@222.76,2812.4 307.4,2812.4 345,2850 R18.1@426.38,2850
  Layer 8 - Bottom Layer w20: v2(395,2850) 395,2829.23 L13.4@400.02,2824.21
CAN2_LOW: C7.1 D6.2 J4.1 L13.3 R23.2 | length 342.3
  Layer 1 - Top Layer w20: J4.1@142.24,2702.01 177.83,2737.6 D6.2@222.76,2737.6 307.4,2737.6 345,2700 v2(395,2700) R23.2@426.38,2700
  Layer 8 - Bottom Layer w20: v2(395,2700) 395,2720.77 L13.3@400.02,2725.79
CAN_EN: U13.6 U14.C17 | length 3454.6
  Layer 1 - Top Layer w8: v2(815,2655) 816.11,2655 831.11,2640 1015,2640 1030,2655 1635,2655 1660,2630 1660,2325 1775,2210 v2(2180,2210)
  Layer 5 - Signal w5: v2(2180,2210) 2195,2195 2195,2155 2235,2115 2900,2115 2985,2200 3440,2200 3529,2289 3546,2289 3558,2277 3611.09,2277 v5(3641.73,2246.35)
  Layer 8 - Bottom Layer w4: v5(3641.73,2246.35) U14.C17@3654.53,2257.01
  Layer 8 - Bottom Layer w8: U13.6@779.06,2705.63 809.37,2705.63 815,2700 v2(815,2655)
CAN_FAULT: U13.8 U14.V12 | length 4226.6
  Layer 5 - Signal w5: v2(660.94,2655) 740.94,2735 985,2735 1495,3245 1495,3290 1555,3350 1660,3350 1725,3285 1875,3285 1960,3200 3565,3200 3785,2980 3785,2915 3750,2880 v5(3525,2880)
  Layer 8 - Bottom Layer w4: 3513.78,2678.61 3513.78,2653.66 U14.V12@3526.57,2640.87
  Layer 8 - Bottom Layer w5.5: 3513.78,2678.61 3513.78,2681.22 3505,2690 3505,2720 3515,2730 3515,2775 3535,2795 3535,2870 v5(3525,2880)
  Layer 8 - Bottom Layer w10: v2(660.94,2655) U13.8@660.94,2685.94
CAN_FD1_RXD: U14.B2 U16.4 | length 2899.2
  Layer 1 - Top Layer w5.5: v2(773.72,2258.72) 773.72,2333.72 805,2365 1045,2365 1080,2330 1120,2330 v2(1175,2385)
  Layer 8 - Bottom Layer w4: 3257.87,2193.35 3257.87,2218.62 U14.B2@3270.67,2231.42
  Layer 8 - Bottom Layer w5.5: U16.4@750.12,2276.61 755.83,2276.61 v2(773.72,2258.72) ; v2(1175,2385) 1430,2385 1610,2205 2018.79,2205 2133.79,2320 2728.93,2320 2888.93,2160 3246.9,2160 3257.87,2170.97 3257.87,2193.35
CAN_FD1_TXD: U14.A2 U16.1 | length 2805.7
  Layer 1 - Top Layer w5.5: v2(773.72,2371.28) 787.44,2385 1070,2385 v2(1100,2355)
  Layer 8 - Bottom Layer w5.5: U16.1@750.12,2353.39 755.83,2353.39 v2(773.72,2371.28) ; v2(1100,2355) 1435,2355 1600,2190 2025,2190 2140,2305 2431.36,2305 ; U14.A2@3270.67,2205.83 3270.67,2165.67 3250,2145 2882.72,2145 2722.72,2305 2460,2305 ; 2431.36,2305 2460,2305 ; 2431.36,2305 2460,2305
CAN_FD2_RXD: U13.4 U14.C1 | length 2920.7
  Layer 8 - Bottom Layer w5.5: U13.4@779.06,2745 885,2745 915,2715 915,2520 995,2440 1425,2440 1595,2270 1810,2270 1830,2250 2000,2250 2115,2365 2747.57,2365 2907.57,2205 3178.02,2205 3230.03,2257.01 U14.C1@3245.08,2257.01
CAN_FD2_TXD: U13.1 U14.B1 | length 3045.2
  Layer 8 - Bottom Layer w5.5: U13.1@779.06,2804.06 749.06,2804.06 735,2790 735,2665 917.5,2482.5 932.5,2482.5 1001.72,2413.28 1426.72,2413.28 1620,2220 2012.57,2220 2127.57,2335 2431.36,2335 ; U14.B1@3245.08,2231.42 3188.66,2175 2895.15,2175 2735.15,2335 2470,2335 ; 2431.36,2335 2470,2335 ; 2431.36,2335 2470,2335
CAN_INH: R207.2 U13.7 | length 1733.1
  Layer 5 - Signal w5: v2(730,1160) 700,1190 700,1520 825,1645 825,2180 875,2230 875,2559.06 v2(779.06,2655)
  Layer 8 - Bottom Layer w10: R207.2@685,1113.62 685,1144.82 700.18,1160 v2(730,1160) ; v2(779.06,2655) U13.7@779.06,2685.94
CAN_nSTB: R221.2 U13.14 | length 3334.8
  Layer 5 - Signal w5: v2(1380,2770) 1565,2585 1565,2410 1665,2310 1665,1775 1730,1710 1905,1710 1967,1648 1967,1388 2195,1160 2195,1025 2310,910 2310,825 2265,780 v2(2225,780)
  Layer 8 - Bottom Layer w8: U13.14@660.94,2804.06 694.06,2804.06 735,2845 1305,2845 v2(1380,2770) ; R221.2@2193.62,780 v2(2225,780)
CBOOT: C217.2 R222.1 U20.4 | length 202.2
  Layer 8 - Bottom Layer w8: R222.1@776.38,650 780,650 800,670 800,695 807.44,702.44 C217.2@807.44,705 ; C217.2@807.44,700 815,707.56 815,726 834,745 857,745 878.05,766.05 U20.4@878.05,789.45
CLKM: C118.1 U14.U1 Y3.3 | length 330.6
  Layer 8 - Bottom Layer w5.5: Y3.3@2999.32,2785.82 3004.5,2791 3054,2791 C118.1@3125,2720 ; C118.1@3119.49,2709.49 3130,2720 3140.35,2720 U14.U1@3245.08,2615.28
CLKP: C115.1 U14.V1 Y3.1 | length 280.1
  Layer 8 - Bottom Layer w5.5: C115.1@3151.7,2848.3 3110.68,2807.27 3110.68,2775.27 U14.V1@3245.08,2640.87
DSS_UARTA_RX: TP12.1 U14.H19 | length 266.9
  Layer 8 - Bottom Layer w5.5: U14.H19@3705.71,2384.96 3725.02,2384.96 3733.82,2393.76 3881.24,2393.76 3905,2370 3940,2370 3950,2380 TP12.1@3950,2385
DSS_UARTA_TX: TP11.1 U14.J19 | length 255.3
  Layer 8 - Bottom Layer w5.5: U14.J19@3705.71,2410.55 3721.4,2410.55 3727.61,2416.76 3941.76,2416.76 3950,2425 TP11.1@3950,2430
EMU0: J3.13 R124.1 | length 94.9
  Layer 8 - Bottom Layer w8: J3.13@4821.5,3000 R124.1@4916.38,3000
EMU1: J3.14 R123.1 | length 94.9
  Layer 8 - Bottom Layer w8: R123.1@4513.62,3000 J3.14@4608.5,3000
EPWMA0: R126.1 U14.E3 | length 1949.3
  Layer 3 - Signal (Sensitive) w5: v2(1745,2855) 1960,2855 2025,2790 2025,2690 2115,2600 2115,2480 2170,2425 2930,2425 2960,2395 3100,2395 3199.61,2295.39 v5(3285.61,2295.39)
  Layer 8 - Bottom Layer w4: v5(3285.61,2295.39) U14.E3@3296.26,2308.19
  Layer 8 - Bottom Layer w5: R126.1@1713.62,2855 v2(1745,2855)
ETH_CLKOUT: R7.1 TP43.1 U10.16 | length 373.7
  Layer 1 - Top Layer w8: TP43.1@1410,3625 1580,3625 1595,3610 1595,3593.62 R7.1@1598.62,3590 R7.1@1598.62,3588.62 ; v2(1600,3530) 1600,3590 R7.1@1598.62,3588.62 ; R7.1@1598.62,3588.62 1598.62,3585 1596.81,3586.81 R7.1@1598.62,3588.62
  Layer 8 - Bottom Layer w8: v2(1600,3530) 1600,3478 1614.63,3463.37 U10.16@1630.83,3463.37
ETH_GPIO0: R13.2 R85.2 U10.35 | length 2036
  Layer 1 - Top Layer w8: v2(500,3795) 615,3680 810,3680 1000,3490 1140,3490 1455,3805 1615,3805 1720,3700 1720,3595 1858.62,3456.38 R13.2@1858.62,3364 1859.62,3365 1885,3365 v2(1895,3355)
  Layer 8 - Bottom Layer w8: v2(500,3795) R85.2@500,3836.38 ; U10.35@1859.17,3364.94 1884.94,3364.94 1894.89,3355 v2(1895,3355)
ETH_GPIO1: R14.1 R86.2 U10.6 | length 2250.9
  Layer 1 - Top Layer w8: v2(395,3795) 530,3660 800,3660 990,3470 1150,3470 1465,3785 1605,3785 1700,3690 1700,3515 1650,3465 1650,3350 1689.19,3310.81 R14.1@1745,3310.81 1745,3270 v2(1725.31,3250.32)
  Layer 8 - Bottom Layer w8: v2(395,3795) R86.2@395,3836.38 ; v2(1725.31,3250.32) U10.6@1725.31,3309.83
ETH_TRD_N: C101.2 R103.1 R105.2 | length 128.4
  Layer 8 - Bottom Layer w5: R103.1@1461.5,3425 1462.48,3425 1486.98,3400.5 1498.06,3400.5 C101.2@1515,3417.44 ; C101.2@1515,3421.38 C101.2@1515,3417.44 ; R105.2@1557.01,3412 1545.51,3400.5 1531.94,3400.5 C101.2@1515,3417.44
ETH_TRD_P: C105.1 R108.1 R109.2 | length 128.4
  Layer 8 - Bottom Layer w5: R108.1@1461.5,3365 1462.48,3365 1486.98,3389.5 1498.06,3389.5 C105.1@1515,3372.56 ; C105.1@1515,3368.62 C105.1@1515,3372.56 ; R109.2@1557.01,3378 1545.51,3389.5 1531.94,3389.5 C105.1@1515,3372.56
ETH_XI: R116.1 U10.5 | length 113.3
  Layer 8 - Bottom Layer w8: U10.5@1745,3309.83 1745,3266.72 1764,3247.72 1764,3229.56 1749,3214.56 R116.1@1749,3210.62
ETH_XO: R115.2 U10.4 | length 113.4
  Layer 8 - Bottom Layer w8: U10.4@1764.68,3309.83 1765,3309.51 1765,3275 1784,3256 1784,3229.56 1799,3214.56 R115.2@1799,3210.62
ETHERNET_EN: R17.2 R218.2 U10.3 | length 3437.6
  Layer 1 - Top Layer w8: v2(1815,3255) R17.2@1815,3280
  Layer 5 - Signal w5: v2(1815,3255) 1770,3210 1550,3210 1355,3015 1355,2755 1545,2565 1545,2405 1645,2305 1645,1765 1720,1690 1895,1690 1947,1638 1947,1381.28 2135,1193.28 2135,1060 2290,905 2290,830 2270,810 2240,810 v2(2225,825)
  Layer 8 - Bottom Layer w8: U10.3@1784.37,3309.83 1784.37,3285.63 v2(1815,3255) ; R218.2@2193.62,825 v2(2225,825)
ETHERNET_INH: R206.2 U10.10 U14.G3 | length 5042
  Layer 3 - Signal (Sensitive) w5: v2(1630.83,3325) 1800,3325 2045,3080 2045,2700 2132.5,2612.5 2132.5,2482.5 2175,2440 2935,2440 2965,2410 3110,2410 3173.42,2346.58 v5(3285.61,2346.58)
  Layer 5 - Signal w5: v2(770,1160) 750,1180 750,1530 850,1630 850,1765 892,1807 892,2612 1520,3240 1520,3280 1565,3325 v2(1630.83,3325)
  Layer 8 - Bottom Layer w4: v5(3285.61,2346.58) U14.G3@3296.26,2359.37
  Layer 8 - Bottom Layer w8: v2(1630.83,3325) U10.10@1630.83,3345.26
  Layer 8 - Bottom Layer w10: R206.2@730,1113.62 730,1131.42 739.67,1141.08 751.08,1141.08 v2(770,1160)
ETHERNET_nINT: U10.2 U14.B17 | length 4880.4
  Layer 3 - Signal (Sensitive) w5: v2(3455,3810) 3825,3810 4160,3475 4160,2670 3980,2490 3980,2430 v7(3990,2420)
  Layer 8 - Bottom Layer w4: U14.B17@3654.53,2231.42 3667.32,2218.62 3667.32,2197.68
  Layer 8 - Bottom Layer w5.5: 3667.32,2197.68 3710,2155 3950,2155 3975,2180 3975,2235 3995,2255 4071,2255 4085,2269 4125,2269 4135,2279 4135,2310 4025,2420 v7(3990,2420)
  Layer 8 - Bottom Layer w8: U10.2@1804.06,3309.83 1804.06,3290.94 1815,3280 1835,3280 1850,3265 1850,3220 1890,3180 2715,3180 3020,3485 3135,3485 3225,3575 3225,3695 3340,3810 v2(3455,3810)
FB: R63.1 R66.2 R68.1 U20.7 | length 163.8
  Layer 1 - Top Layer w10: R63.1@768.62,920 R68.1@768.62,825 v2(795,825)
  Layer 8 - Bottom Layer w8: v2(795,825) 810,825 815.31,830.32 U20.7@835.21,830.32
FB_B1: R226.2 U21.7 | length 682.2
  Layer 3 - Signal (Sensitive) w10: v2(1975,315) 1965,325 1965,420 1995,450 2110,450 2135,475 2135,528.28 2065,598.28 2065,630 2085,650 2100,650 v2(2120,670)
  Layer 8 - Bottom Layer w8: v2(1975,315) 1975,346.38 R226.2@1980,351.38 ; U21.7@2040.63,670.63 2072.37,670.63 2081,662 2112,662 v2(2120,670)
FB_B2: R227.2 U21.6 | length 657.4
  Layer 3 - Signal (Sensitive) w10: v2(1935,315) 1945,325 1945,428.28 1986.72,470 2100,470 2115,485 2115,520 2045,590 2045,640 v2(2090,685)
  Layer 8 - Bottom Layer w8: R227.2@1930,351.38 1935,346.38 v2(1935,315) ; U21.6@2031.77,690.32 2081.44,690.31 2086.75,685 v2(2090,685)
FB_B3: R210.2 U21.23 | length 608.4
  Layer 3 - Signal (Sensitive) w10: v2(1810,750) 1834.17,774.17 1834.17,832.54 1775,891.72 1775,933.28 1811.72,970 1885,970 1945,1030 1945,1095 v2(1935,1105)
  Layer 8 - Bottom Layer w8: v2(1810,750) 1814,754 1836,754 1840.63,749.37 U21.23@1869.37,749.37 ; R210.2@1930,1068.62 1935,1073.62 v2(1935,1105)
FB_B4: R209.2 U21.22 | length 609.7
  Layer 3 - Signal (Sensitive) w10: v2(1830,730) 1849.17,749.17 1849.17,845.83 1795,900 1795,925 1820,950 1893.28,950 1965,1021.72 1965,1095 v2(1975,1105)
  Layer 8 - Bottom Layer w8: v2(1830,730) 1877.91,730 U21.22@1878.23,729.68 ; v2(1975,1105) 1975,1073.62 R209.2@1980,1068.62
FE1_1V8_FILTERED: C95.1 C96.1 C97.1 C136.1 C143.1 C149.1 C161.1 C164.1 C165.1 C169.1 C173.1 L7.2 R26.2 U5.B11 U5.B12 U5.D13 U5.F5 U5.K5 U5.K13 | length 430.8
  Layer 1 - Top Layer w7: v4(2412.01,1821.26) U5.K13@2424.8,1834.06 ; v4(2412.01,2051.57) U5.K5@2424.8,2038.78 ; U5.F5@2527.17,2038.78 v4(2539.96,2051.58) ; U5.D13@2578.35,1834.06 v4(2591.14,1821.26) ; U5.B12@2629.53,1859.65 v4(2642.32,1846.85) ; U5.B11@2629.53,1885.24 v4(2642.32,1872.44)
  Layer 1 - Top Layer w20: R26.2@3051.38,2608 v2(3051.38,2655)
  Layer 5 - Signal w15: v4(2412.01,1821.26) 2412.01,1832.01 2427,1847 2487,1847 2505,1865 2522,1865 2540,1847 2593,1847
  Layer 8 - Bottom Layer w12: v4(2412.01,1821.26) 2412.01,1835.59 2423.42,1847.01 C165.1@2427.36,1847.01 ; v4(2539.96,2051.58) 2539.96,2023.66 C149.1@2540,2023.62
  other v2: 2575,200 2605,200 2635,200 1135,220 1165,220 1195,220 1225,220 2575,230 2605,230 2635,230 2280,2200 2310,2200
FE1_CLKOUT_TO_PMIC: J9.3 R193.2 U21.10 | length 3036.6
  Layer 5 - Signal w5: J9.3@1375.98,117.01 1422.99,70 1630,70 1700,140 1985,140 2117.5,272.5 2117.5,412.5 2145,440 2145,520 2120,545 2120,570 v2(2130,580) 2200,580 2240,540 2280,540 2425,685 2425,965 2275,1115 2275,1190 2145,1320 2145,1590 2043,1692 2043,1780 2058,1795 v2(2100,1795)
  Layer 8 - Bottom Layer w8: U21.10@2014.05,612.56 2014.06,587.94 2022,580 v2(2130,580) ; v2(2100,1795) R193.2@2126.38,1795
FE1_CSI2_CLK_N: U5.J14 U14.B6 | length 1726.2
  Layer 1 - Top Layer w7: v4(2437.6,1795.67) U5.J14@2450.39,1808.46
  Layer 3 - Signal (Sensitive) w4: v4(2437.6,1795.67) 2428.96,1787.03 ccw(c2438.98,1777) 2424.8,1777 2424.8,1761.33 ccw(c2429.51,1761.33) 2426.18,1758 cw(c2422.76,1754.58) 2427.6,1754.58 2427.6,1712.87 ccw(c2462.87,1712.87) 2437.93,1687.93 2487.93,1637.93 ccw(c2507.07,1657.07) 2507.07,1630 2525,1630 ccw(c2525,1676.21) 2557.68,1643.54 2567.07,1652.93 ; 2567.08,1652.94 cw(c2584.14,1635.86) 2584.14,1660 2662.93,1660 cw(c2662.93,1642.93) 2675,1655 2684.39,1645.61 ccw(c2710,1671.21) 2710,1635 2720,1635 2734.86,1635 ccw(c2734.86,1679.14) 2766.07,1647.93 2780.07,1661.93 ccw(c2744.03,1697.97) 2795,1697.97 2795,1703.99 cw(c2824.01,1703.99) 2803.49,1724.49 ; 2803.5,1724.5 2830.96,1751.96 ccw(c2772.92,1810) 2855,1810 2855,1925 cw(c2895,1925) 2895,1965 2907.83,1965 cw(c2907.83,1942.83) 2930,1942.83 2930,1934.49 cw(c2919.51,1934.49) 2926.93,1927.07 ccw(c2941.24,1912.76) 2921,1912.76 2921,1901.14 ccw(c2952.14,1901.14) 2952.14,1870 3130.86,1870 ccw(c3130.86,1892.41) 3146.71,1876.57 3150.29,1880.15 cw(c3162,1868.44) 3162,1885 3170.86,1885 ccw(c3170.86,1909.14) 3195,1909.14 3195,1935 cw(c3203.66,1935) 3203.66,1943.66 3222,1943.66 cw(c3222,1929.18) 3232.24,1939.42 v2(3238.5,1933.16)
  Layer 8 - Bottom Layer w4: v2(3238.5,1933.16) 3245.17,1939.83 cw(c3252,1933.01) 3252,1942.66 3262,1942.66 ccw(c3262,1959.66) 3279,1959.66 3279,1992.49 cw(c3317.51,1992.49) 3290.28,2019.72 3367.23,2096.67 ccw(c3322.33,2141.57) 3385.83,2141.57 3385.83,2218.62 U14.B6@3373.03,2231.42
FE1_CSI2_CLK_P: U5.J15 U14.A6 | length 1726.5
  Layer 1 - Top Layer w7: v4(2437.6,1770.08) U5.J15@2450.39,1782.87
  Layer 3 - Signal (Sensitive) w4: v4(2437.6,1770.08) 2437.6,1712.87 ccw(c2462.87,1712.87) 2445,1695 2495,1645 ccw(c2507.07,1657.07) 2507.07,1640 2525,1640 ccw(c2525,1676.21) 2550.61,1650.61 2560,1660 cw(c2584.14,1635.86) 2584.14,1670 2662.93,1670 cw(c2662.93,1642.93) 2682.07,1662.07 2691.46,1652.68 ccw(c2710,1671.21) 2710,1645 2734.86,1645 ccw(c2734.86,1679.14) 2759,1655 2773,1669 ccw(c2744.03,1697.97) 2785,1697.97 2785,1703.99 cw(c2824.01,1703.99) 2796.42,1731.57 2823.89,1759.03 ccw(c2772.92,1810) 2845,1810 2845,1925 cw(c2895,1925) 2895,1975 2907.83,1975 cw(c2907.83,1942.83) 2940,1942.83 2940,1934.49 cw(c2919.51,1934.49) 2934,1920 ccw(c2941.24,1912.76) 2931,1912.76 2931,1901.14 ccw(c2952.14,1901.14) 2952.14,1880 2998.17,1880 ccw(c2998.17,1886.83) 3005,1886.83 3005,1904 cw(c3013,1904) 3013,1912 3026,1912 cw(c3026,1903) 3035,1903 3035,1886.83 ccw(c3041.83,1886.83) 3041.83,1880 3073.53,1880 ccw(c3073.53,1891.47) 3085,1891.47 3085,1898.34 cw(c3098.66,1898.34) 3098.66,1912 3101.34,1912 cw(c3101.34,1898.34) 3115,1898.34 3115,1887.83 ccw(c3122.83,1887.83) 3122.83,1880 3130.86,1880 ccw(c3130.86,1892.41) 3139.64,1883.64 3143.22,1887.22 cw(c3162,1868.44) 3162,1895 3170.86,1895 ccw(c3170.86,1909.14) 3185,1909.14 3185,1935 cw(c3203.66,1935) 3203.66,1953.66 3219,1953.66 3222,1953.66 ccw(c3222,1968.15) 3232.23,1957.9 v2(3238,1963.66)
  Layer 8 - Bottom Layer w4: v2(3238,1963.66) 3245.17,1956.49 ccw(c3252,1963.32) 3252,1953.66 3261.17,1953.66 ccw(c3261.17,1960.49) 3268,1960.49 3268,1992.49 cw(c3317.5,1992.49) 3282.5,2027.5 3359.45,2104.45 ccw(c3322.33,2141.57) 3374.83,2141.57 3374.83,2192.06 3373.03,2193.85 U14.A6@3373.03,2205.83
FE1_CSI2_TX0_N: U5.G14 U14.A8 | length 1726.2
  Layer 1 - Top Layer w7: v4(2488.78,1821.26) U5.G14@2501.57,1808.46
  Layer 3 - Signal (Sensitive) w4: v4(2488.78,1821.26) 2497.42,1812.62 cw(c2487.39,1802.59) 2501.57,1802.59 ccw(c2515.03,1802.59) 2505.51,1793.08 2531.1,1767.49 2544.3,1754.3 ccw(c2569.15,1779.15) 2569.15,1744 2670,1744 ccw(c2670,1779) 2705,1779 2705,1807 cw(c2743,1807) 2743,1845 ccw(c2743,1867) 2765,1867 2765,2073.58 cw(c2836.37,2073.58) 2785.9,2124.05 2802.64,2140.78 cw(c2880.42,2063) 2880.42,2173 2948.48,2173 cw(c2948.48,2071.48) 3050,2071.48 3050,2030 ccw(c3060,2030) 3060,2020 3076.54,2020 ccw(c3076.54,2028.46) 3085,2028.46 3085,2036.54 cw(c3093.46,2036.54) 3093.46,2045 3104.76,2045 cw(c3104.76,2034.76) 3115,2034.76 3115,2028.46 ccw(c3123.46,2028.46) 3123.46,2020 3137.03,2020 ccw(c3137.03,2060.97) 3165.99,2031.99 3177,2043 cw(c3218.04,2001.96) 3218.04,2060 3340,2060 cw(c3340,2030) 3370,2030 3370,2015 ccw(c3380,2015) 3380,2005 3384,2005 ccw(c3384,2019.49) 3394.23,2009.23 v2(3400,2015)
  Layer 8 - Bottom Layer w4: v2(3400,2015) 3407.17,2007.83 ccw(c3414,2014.66) 3414,2005 3418,2005 ccw(c3418,2013.01) 3426.01,2013.01 3426.01,2192.06 3424.21,2193.85 U14.A8@3424.21,2205.83
FE1_CSI2_TX0_P: U5.G15 U14.B8 | length 1726.5
  Layer 1 - Top Layer w7: v4(2488.78,1795.67) U5.G15@2501.57,1782.87
  Layer 3 - Signal (Sensitive) w4: v4(2488.78,1795.67) 2537.22,1747.22 ccw(c2569.15,1779.15) 2569.15,1734 2670,1734 ccw(c2670,1779) 2715,1779 2715,1807 cw(c2743,1807) 2743,1835 ccw(c2743,1867) 2775,1867 2775,2073.58 cw(c2836.37,2073.58) 2792.98,2116.98 2809.71,2133.71 cw(c2880.42,2063) 2880.42,2163 2948.48,2163 cw(c2948.48,2071.48) 3040,2071.48 3040,2030 ccw(c3060,2030) 3060,2010 3137.03,2010 ccw(c3137.03,2060.97) 3173.07,2024.93 3184.07,2035.93 cw(c3218.04,2001.96) 3218.04,2050 3340,2050 cw(c3340,2030) 3360,2030 3360,2015 ccw(c3380,2015) 3380,1995 3384,1995 cw(c3384,1980.52) 3394.24,1990.76 v2(3400.5,1984.5)
  Layer 8 - Bottom Layer w4: v2(3400.5,1984.5) 3407.17,1991.17 cw(c3414,1984.34) 3414,1994 3418,1994 ccw(c3418,2013.01) 3437.01,2013.01 3437.01,2218.62 U14.B8@3424.21,2231.42
FE1_CSI2_TX1_N: U5.H14 U14.A7 | length 1725.9
  Layer 1 - Top Layer w7: v4(2463.19,1795.67) U5.H14@2475.98,1808.46
  Layer 3 - Signal (Sensitive) w4: v4(2463.19,1795.67) 2471.83,1787.03 cw(c2461.8,1777) 2475.98,1777 2475.98,1761.33 cw(c2471.28,1761.33) 2474.61,1758 ccw(c2478.03,1754.58) 2473.19,1754.58 2473.19,1739.79 ccw(c2528.66,1739.79) 2489.44,1700.56 2502.93,1687.07 ccw(c2520,1704.14) 2520,1680 2525,1680 ccw(c2525,1692.07) 2533.54,1683.54 2545,1695 cw(c2581.21,1658.79) 2581.21,1710 2685,1710 ccw(c2685,1746.21) 2710.61,1720.61 2740,1750 ccw(c2715.86,1774.14) 2750,1774.14 2750,1780 cw(c2772.07,1780) 2756.46,1795.61 2795.43,1834.57 ccw(c2772.32,1857.68) 2805,1857.68 2805,1975 cw(c2830,1975) 2830,2000 2845,2000 ccw(c2845,2020) 2865,2020 2865,2026.25 ccw(c2846.25,2026.25) 2846.25,2045 2839.14,2045 cw(c2839.14,2064.14) 2820,2064.14 2820,2071.63 cw(c2850.37,2071.63) 2850.37,2102 2855,2102 cw(c2855,2060.61) 2884.26,2089.88 2917.32,2056.82 ; 2917.34,2056.8 ccw(c2970,2109.5) 2970,2035 2981.25,2035 cw(c2981.25,2006.25) 3010,2006.25 3010,1987.75 ccw(c3047.75,1987.75) 3047.75,1950 3074.76,1950 ccw(c3074.76,1960.24) 3085,1960.24 3085,1965 cw(c3095,1965) 3095,1975 3105,1975 cw(c3105,1965) 3115,1965 3115,1961.9 ccw(c3126.9,1961.9) 3126.9,1950 3128,1950 ccw(c3128,1976.56) 3146.78,1957.78 3171,1982 cw(c3226.53,1926.47) 3226.53,2005 3314,2005 ccw(c3314,2019.49) 3324.23,2009.23 v2(3330,2015)
  Layer 8 - Bottom Layer w4: v2(3330,2015) 3337.17,2007.83 ccw(c3344,2014.66) 3344,2005 3353.17,2005 ccw(c3353.17,2011.83) 3360,2011.83 3360,2026.81 cw(c3393.19,2026.81) 3369.72,2050.27 3386.96,2067.52 ccw(c3354.48,2100) 3400.42,2100 3400.42,2192.06 3398.62,2193.85 U14.A7@3398.62,2205.83
FE1_CSI2_TX1_P: U5.H15 U14.B7 | length 1726.4
  Layer 1 - Top Layer w7: v4(2463.19,1770.08) U5.H15@2475.98,1782.87
  Layer 3 - Signal (Sensitive) w4: v4(2463.19,1770.08) 2463.19,1739.79 ccw(c2528.66,1739.79) 2482.37,1693.49 2495.86,1680 ccw(c2520,1704.14) 2520,1670 2525,1670 ccw(c2525,1692.07) 2540.61,1676.46 2552.07,1687.93 cw(c2581.21,1658.79) 2581.21,1700 2685,1700 ccw(c2685,1746.21) 2717.68,1713.54 2747.07,1742.93 ccw(c2715.86,1774.14) 2760,1774.14 2760,1780 cw(c2772.07,1780) 2763.54,1788.54 2802.5,1827.5 ccw(c2772.32,1857.68) 2815,1857.68 2815,1975 cw(c2830,1975) 2830,1990 2845,1990 ccw(c2845,2020) 2875,2020 2875,2026.25 ccw(c2846.25,2026.25) 2846.25,2055 2839.14,2055 cw(c2839.14,2064.14) 2830,2064.14 2830,2071.63 cw(c2850.37,2071.63) 2850.37,2092 2855,2092 cw(c2855,2060.62) 2877.19,2082.81 2910.25,2049.75 ccw(c2970,2109.5) 2970,2025 2981.25,2025 cw(c2981.25,2006.25) 3000,2006.25 3000,1987.75 ccw(c3047.75,1987.75) 3047.75,1940 3128,1940 ccw(c3128,1976.56) 3153.85,1950.71 3178.07,1974.93 cw(c3226.53,1926.47) 3226.53,1995 3314,1995 cw(c3314,1980.52) 3324.24,1990.76 v2(3330.5,1984.5)
  Layer 8 - Bottom Layer w4: v2(3330.5,1984.5) 3337.17,1991.17 cw(c3344,1984.34) 3344,1994 3354,1994 ccw(c3354,2011) 3371,2011 3371,2026.81 cw(c3393.19,2026.81) 3377.5,2042.5 3394.74,2059.74 ccw(c3354.48,2100) 3411.42,2100 3411.42,2218.62 U14.B7@3398.62,2231.42
FE1_CSI2_TX2_N: U5.K14 U14.B5 | length 1726.3
  Layer 1 - Top Layer w7: v4(2412.01,1795.67) U5.K14@2424.8,1808.46
  Layer 3 - Signal (Sensitive) w4: v4(2412.01,1795.67) 2403.37,1787.03 ccw(c2413.39,1777) 2399.21,1777 2399.21,1761.33 ccw(c2403.92,1761.33) 2400.59,1758 cw(c2397.17,1754.58) 2402.01,1754.58 2402.01,1732.85 cw(c2395.15,1732.85) 2400,1728 ccw(c2412.07,1715.93) 2395,1715.93 2395,1700 ccw(c2443.63,1700) 2409.24,1665.62 2506.78,1568.08 ccw(c2550.43,1611.73) 2550.43,1550 2556.49,1550 ccw(c2556.49,1573.51) 2580,1573.51 2580,1602.93 cw(c2597.07,1602.93) 2597.07,1620 2626.34,1620 cw(c2626.34,1606.34) 2640,1606.34 2640,1571.76 ccw(c2661.76,1571.76) 2661.76,1550 2700,1550 ccw(c2700,1608.28) 2741.21,1567.07 2966.46,1792.32 cw(c2985,1773.79) 2985,1800 3125,1800 ccw(c3125,1817.24) 3137.19,1805.05 3165.44,1833.3 cw(c3180,1818.75) 3180,1839.33 3183,1839.33 cw(c3183,1824.85) 3193.24,1835.09 v2(3199.5,1828.83)
  Layer 8 - Bottom Layer w4: v2(3199.5,1828.83) 3206.17,1835.5 cw(c3213,1828.67) 3213,1838.33 3223,1838.33 ccw(c3223,1855.33) 3240,1855.33 3240,1859.89 ccw(c3186.89,1859.89) 3224.44,1897.44 3222.78,1899.11 cw(c3268.11,1944.44) 3204,1944.44 3204,1967 cw(c3243.7,1967) 3215.63,1995.07 3345.87,2125.31 ccw(c3311.18,2160) 3360.24,2160 3360.24,2218.62 U14.B5@3347.44,2231.42
FE1_CSI2_TX2_P: U5.K15 U14.A5 | length 1726.2
  Layer 1 - Top Layer w7: v4(2412.01,1770.08) U5.K15@2424.8,1782.87
  Layer 3 - Signal (Sensitive) w4: v4(2412.01,1770.08) 2412.01,1732.85 cw(c2395.15,1732.85) 2407.07,1720.93 ccw(c2412.07,1715.93) 2405,1715.93 2405,1700 ccw(c2443.63,1700) 2416.3,1672.7 2513.85,1575.15 ccw(c2550.43,1611.73) 2550.43,1560 2556.34,1560 ccw(c2556.34,1573.66) 2570,1573.66 2570,1602.93 cw(c2597.07,1602.93) 2597.07,1630 2626.34,1630 cw(c2626.34,1606.34) 2650,1606.34 2650,1571.9 ccw(c2661.9,1571.9) 2661.9,1560 2700,1560 ccw(c2700,1608.28) 2734.14,1574.14 2959.39,1799.39 cw(c2985,1773.79) 2985,1810 2995,1810 ccw(c2995,1820) 3005,1820 3005,1831.76 cw(c3015.24,1831.76) 3015.24,1842 3023.1,1842 cw(c3023.1,1830.1) 3035,1830.1 3035,1820 ccw(c3045,1820) 3045,1810 3076.54,1810 ccw(c3076.54,1818.46) 3085,1818.46 3085,1832 cw(c3095,1832) 3095,1842 3106,1842 cw(c3106,1833) 3115,1833 3115,1818.46 ccw(c3123.46,1818.46) 3123.46,1810 3125,1810 ccw(c3125,1817.24) 3130.12,1812.12 3158.37,1840.37 cw(c3180,1818.75) 3180,1849.33 3183,1849.33 ccw(c3183,1863.82) 3193.23,1853.57 v2(3199,1859.33)
  Layer 8 - Bottom Layer w4: v2(3199,1859.33) 3206.17,1852.16 ccw(c3213,1858.99) 3213,1849.33 3222.17,1849.33 ccw(c3222.17,1856.16) 3229,1856.16 3229,1859.89 ccw(c3186.89,1859.89) 3216.67,1889.67 3215,1891.33 cw(c3268.11,1944.44) 3193,1944.44 3193,1967 cw(c3243.7,1967) 3207.83,2002.83 3338.09,2133.09 ccw(c3311.18,2160) 3349.24,2160 3349.24,2192.06 3347.44,2193.85 U14.A5@3347.44,2205.83
FE1_CSI2_TX3_N: U5.L14 U14.B4 | length 1725.9
  Layer 1 - Top Layer w7: v4(2386.42,1795.67) U5.L14@2399.21,1808.46
  Layer 3 - Signal (Sensitive) w4: v4(2386.42,1795.67) 2377.78,1787.03 ccw(c2387.8,1777) 2373.62,1777 2373.62,1761.33 ccw(c2378.33,1761.33) 2375,1758 cw(c2371.58,1754.58) 2376.42,1754.58 2376.42,1752 cw(c2365.7,1752) 2373.28,1744.42 2367.88,1739.02 ccw(c2386.9,1720) 2360,1720 2360,1692.63 ccw(c2439.11,1692.63) 2383.17,1636.69 2495.93,1523.93 ccw(c2517.49,1545.49) 2517.49,1515 2727.93,1515 ccw(c2727.93,1542.07) 2747.07,1522.93 2930.36,1706.22 cw(c2999.84,1636.74) 2999.84,1735 3144,1735 cw(c3144,1720.51) 3154.24,1730.76 v2(3160.5,1724.5)
  Layer 8 - Bottom Layer w4: v2(3160.5,1724.5) 3167.17,1731.17 cw(c3174,1724.34) 3174,1734 3184,1734 ccw(c3184,1751) 3201,1751 3201,1755.56 ccw(c3147.89,1755.56) 3185.44,1793.11 3183.78,1794.78 cw(c3229.11,1840.11) 3165,1840.11 3165,1976.58 cw(c3208.13,1976.58) 3177.63,2007.08 3323.4,2152.84 ccw(c3296.24,2180) 3334.65,2180 3334.65,2218.62 U14.B4@3321.85,2231.42
FE1_CSI2_TX3_P: U5.L15 U14.A4 | length 1726.2
  Layer 1 - Top Layer w7: v4(2386.42,1770.08) U5.L15@2399.21,1782.87
  Layer 3 - Signal (Sensitive) w4: v4(2386.42,1770.08) 2386.42,1752 cw(c2365.7,1752) 2380.35,1737.35 2374.95,1731.95 ccw(c2386.9,1720) 2370,1720 2370,1692.63 ccw(c2439.11,1692.63) 2390.24,1643.76 2503,1531 ccw(c2517.49,1545.49) 2517.49,1525 2727.93,1525 ccw(c2727.93,1542.07) 2739.99,1529.99 2923.29,1713.29 cw(c2999.84,1636.74) 2999.84,1745 3009.76,1745 ccw(c3009.76,1755.24) 3020,1755.24 3020,1768.54 cw(c3028.46,1768.54) 3028.46,1777 3041,1777 cw(c3041,1768) 3050,1768 3050,1756.9 ccw(c3061.9,1756.9) 3061.9,1745 3089.76,1745 ccw(c3089.76,1755.24) 3100,1755.24 3100,1769 cw(c3108,1769) 3108,1777 3121,1777 cw(c3121,1768) 3130,1768 3130,1755.24 ccw(c3140.24,1755.24) 3140.24,1745 3144,1745 ccw(c3144,1759.49) 3154.23,1749.23 v2(3160,1755)
  Layer 8 - Bottom Layer w4: v2(3160,1755) 3167.17,1747.83 ccw(c3174,1754.66) 3174,1745 3183.17,1745 ccw(c3183.17,1751.83) 3190,1751.83 3190,1755.56 ccw(c3147.89,1755.56) 3177.67,1785.33 3176,1787 cw(c3229.11,1840.11) 3154,1840.11 3154,1976.58 cw(c3208.13,1976.58) 3169.85,2014.85 3315.62,2160.62 ccw(c3296.24,2180) 3323.65,2180 3323.65,2192.06 3321.85,2193.85 U14.A4@3321.85,2205.83
FE1_FM_CW_CLKOUT_to_FE2_FM_CW_SYNC_IN: U5.D1 U6.D15 | length 2704.2
  Layer 1 - Top Layer w10: U5.D1@2578.35,2141.14 2578.35,2169.43 cw(c2638.57,2169.43) 2595.98,2212.01 2666.69,2282.72 cw(c2737.41,2212.01) 2737.41,2312.01 2929.56,2312.01 cw(c2929.56,2212.01) 3000.27,2282.72 3051.69,2231.3 cw(c2980.98,2160.59) 3080.98,2160.59 3080.98,1682.01 ccw(c3145.98,1682.01) 3145.98,1617.01 4408.82,1617.01 ccw(c4408.82,1649.92) 4441.73,1649.92 U6.D15@4441.73,1782.87
FE1_GPIO0: U5.N4 U14.W16 | length 4041.4
  Layer 1 - Top Layer w7: v4(2335.24,2077.17) U5.N4@2348.03,2064.37
  Layer 3 - Signal (Sensitive) w5: v2(1745,2125) 1770,2125 1780,2115 1970,2115 2030,2055 2145,2055 2197,2107 2214,2107 2246,2075 2275,2075 2293.7,2093.7 2318.7,2093.7 v4(2335.24,2077.17)
  Layer 5 - Signal w5: v2(1745,2125) 1725,2145 1725,2325 1625,2425 1625,2880 1705,2960 2180,2960 2305,3085 3480,3085 3630,2935 v2(3715,2935)
  Layer 8 - Bottom Layer w4: U14.W16@3628.94,2666.46 3628.94,2679.43 3645.7,2696.19
  Layer 8 - Bottom Layer w5.5: 3645.7,2696.19 3655,2705.49 3655,2890 3700,2935 v2(3715,2935)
